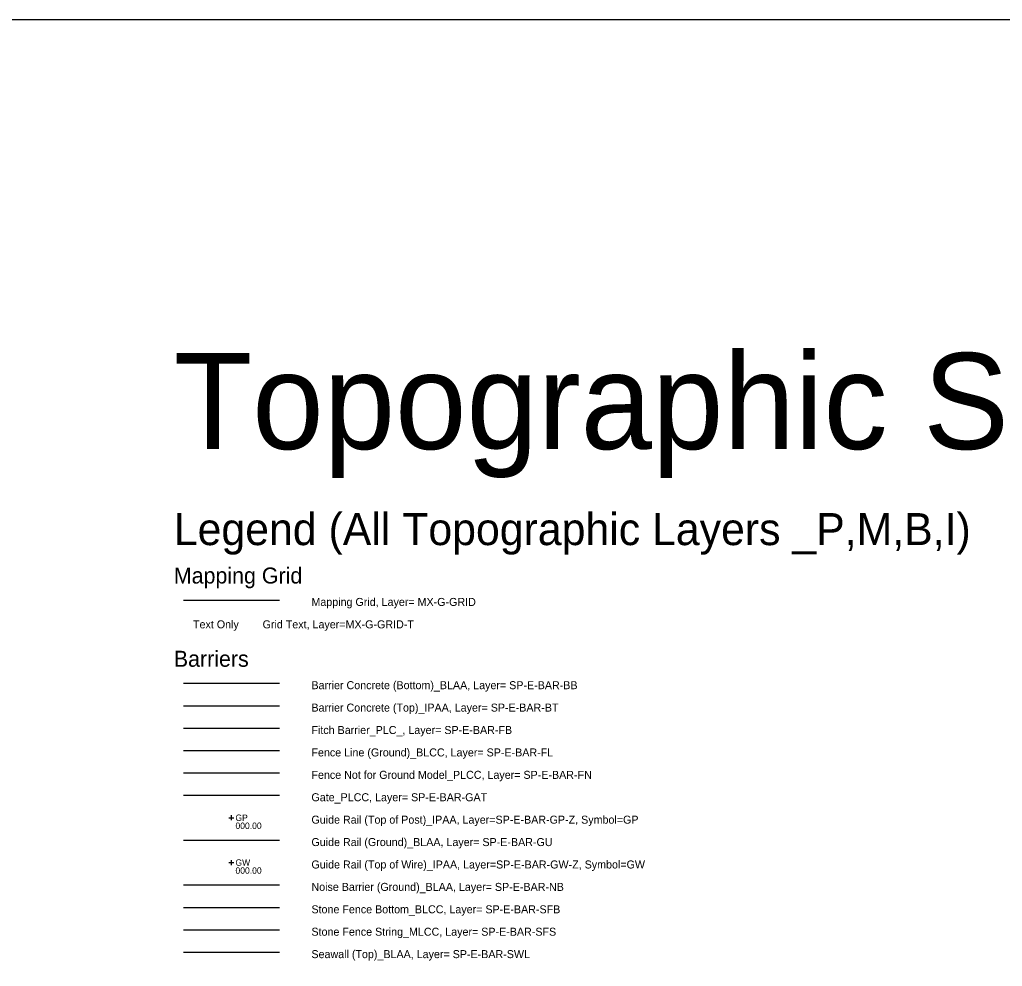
# Model space of a CAD drawing. Extents: x 500528 to 502626, y 4210261 to 4212624.
# Drawn here: x 500835.4 to 501142.4, y 4212328.2 to 4212623.9 of the extents above; entities that cross this region are included whole.
import ezdxf

# ---------------------------------------------------------------- set-up
doc = ezdxf.new("R2010")
doc.units = 0
for name, color, linetype in [('Default', 7, 'Continuous'), ('MX-G-GRID', 7, 'Continuous'), ('MX-G-GRID-T', 7, 'Continuous'), ('SP-E-BAR-BB', 7, 'Continuous'), ('SP-E-BAR-BT', 7, 'Continuous'), ('SP-E-BAR-FB', 7, 'Continuous'), ('SP-E-BAR-FL', 7, 'Continuous'), ('SP-E-BAR-FN', 7, 'Continuous'), ('SP-E-BAR-GAT', 7, 'Continuous'), ('SP-E-BAR-GP-Z', 7, 'Continuous'), ('SP-E-BAR-GU', 7, 'Continuous'), ('SP-E-BAR-GW-Z', 7, 'Continuous'), ('SP-E-BAR-NB', 7, 'Continuous'), ('SP-E-BAR-SFB', 7, 'Continuous'), ('SP-E-BAR-SFS', 7, 'Continuous'), ('SP-E-BAR-SWL', 7, 'Continuous'), ('SP-E-BAR-T', 7, 'Continuous')]:
    doc.layers.add(name, color=color, linetype=linetype)

# ---------------------------------------------------------------- blocks, each defined once
blk = doc.blocks.new('GP')
at = {"layer": 'SP-E-BAR-GP-Z'}
for points in [[(-0.08, 0), (0.08, 0)], [(0, -0.08), (0, 0.08)]]:
    blk.add_lwpolyline(points, dxfattribs=at)
at = {"layer": 'SP-E-BAR-T'}
for s, p in [('GP', (0.126, -0.1)), ('000.00', (0.126, -0.35))]:
    blk.add_text(s, height=0.2, dxfattribs=at).set_placement(p)
blk = doc.blocks.new('GW')
at = {"layer": 'SP-E-BAR-GW-Z'}
for points in [[(-0.08, 0), (0.08, 0)], [(0, -0.08), (0, 0.08)]]:
    blk.add_lwpolyline(points, dxfattribs=at)
at = {"layer": 'SP-E-BAR-T'}
for s, p in [('GW', (0.126, -0.1)), ('000.00', (0.126, -0.35))]:
    blk.add_text(s, height=0.2, dxfattribs=at).set_placement(p)

msp = doc.modelspace()

# ---------------------------------------------------------------- linework, layer by layer
at = {"layer": 'Default'}
msp.add_lwpolyline([(500528.35, 4212623.85), (500528.35, 4210260.5), (502626.48, 4210260.5), (502626.48, 4212623.85), (500528.35, 4212623.85)], dxfattribs=at)
msp.add_lwpolyline([(500528.35, 4210260.5), (502626.48, 4210260.5), (502626.48, 4212623.85), (500528.35, 4212623.85)], close=True, dxfattribs=at)
at = {"layer": 'MX-G-GRID'}
msp.add_line((500886.55, 4212442.59), (500916.55, 4212442.59), dxfattribs=at)
at = {"layer": 'SP-E-BAR-BB'}
msp.add_line((500886.55, 4212416.59), (500916.55, 4212416.59), dxfattribs=at)
at = {"layer": 'SP-E-BAR-BT'}
msp.add_line((500886.55, 4212409.59), (500916.55, 4212409.59), dxfattribs=at)
at = {"layer": 'SP-E-BAR-FB'}
msp.add_line((500886.55, 4212402.59), (500916.55, 4212402.59), dxfattribs=at)
at = {"layer": 'SP-E-BAR-FL'}
msp.add_line((500886.55, 4212395.59), (500916.55, 4212395.59), dxfattribs=at)
at = {"layer": 'SP-E-BAR-FN'}
msp.add_line((500886.55, 4212388.59), (500916.55, 4212388.59), dxfattribs=at)
at = {"layer": 'SP-E-BAR-GAT'}
msp.add_line((500886.55, 4212381.59), (500916.55, 4212381.59), dxfattribs=at)
at = {"layer": 'SP-E-BAR-GU'}
msp.add_line((500886.55, 4212367.59), (500916.55, 4212367.59), dxfattribs=at)
at = {"layer": 'SP-E-BAR-NB'}
msp.add_line((500886.55, 4212353.59), (500916.55, 4212353.59), dxfattribs=at)
at = {"layer": 'SP-E-BAR-SFB'}
msp.add_line((500886.55, 4212346.59), (500916.55, 4212346.59), dxfattribs=at)
at = {"layer": 'SP-E-BAR-SFS'}
msp.add_line((500886.55, 4212339.59), (500916.55, 4212339.59), dxfattribs=at)
at = {"layer": 'SP-E-BAR-SWL'}
msp.add_line((500886.55, 4212332.59), (500916.55, 4212332.59), dxfattribs=at)

# ---------------------------------------------------------------- block references
at = {"layer": 'SP-E-BAR-GP-Z', "xscale": 10, "yscale": 10}
msp.add_blockref('GP', (500901.55, 4212374.59), dxfattribs=at)
at = {"layer": 'SP-E-BAR-GW-Z', "xscale": 10, "yscale": 10}
msp.add_blockref('GW', (500901.55, 4212360.59), dxfattribs=at)

# ---------------------------------------------------------------- texts
at = {"layer": 'Default'}
for s, height, p in [('Topographic Survey Legend _Rev0 ', 30, (500883.55, 4212489.74)), ('Legend (All Topographic Layers _P,M,B,I) ', 10, (500883.55, 4212459.74)), ('Mapping Grid ', 5, (500883.55, 4212447.74)), ('Barriers ', 5, (500883.55, 4212421.74))]:
    msp.add_text(s, height=height, dxfattribs=at).set_placement(p)
at = {"layer": 'MX-G-GRID'}
msp.add_text('Mapping Grid, Layer= MX-G-GRID ', height=2.5, dxfattribs=at).set_placement((500926.55, 4212440.74))
at = {"layer": 'MX-G-GRID-T'}
msp.add_text('Text Only        Grid Text, Layer=MX-G-GRID-T', height=2.5, dxfattribs=at).set_placement((500889.55, 4212433.74))
at = {"layer": 'SP-E-BAR-BB'}
msp.add_text('Barrier Concrete (Bottom)_BLAA, Layer= SP-E-BAR-BB ', height=2.5, dxfattribs=at).set_placement((500926.55, 4212414.74))
at = {"layer": 'SP-E-BAR-BT'}
msp.add_text('Barrier Concrete (Top)_IPAA, Layer= SP-E-BAR-BT ', height=2.5, dxfattribs=at).set_placement((500926.55, 4212407.74))
at = {"layer": 'SP-E-BAR-FB'}
msp.add_text('Fitch Barrier_PLC_, Layer= SP-E-BAR-FB ', height=2.5, dxfattribs=at).set_placement((500926.55, 4212400.74))
at = {"layer": 'SP-E-BAR-FL'}
msp.add_text('Fence Line (Ground)_BLCC, Layer= SP-E-BAR-FL ', height=2.5, dxfattribs=at).set_placement((500926.55, 4212393.74))
at = {"layer": 'SP-E-BAR-FN'}
msp.add_text('Fence Not for Ground Model_PLCC, Layer= SP-E-BAR-FN ', height=2.5, dxfattribs=at).set_placement((500926.55, 4212386.74))
at = {"layer": 'SP-E-BAR-GAT'}
msp.add_text('Gate_PLCC, Layer= SP-E-BAR-GAT ', height=2.5, dxfattribs=at).set_placement((500926.55, 4212379.74))
at = {"layer": 'SP-E-BAR-GP-Z'}
msp.add_text('Guide Rail (Top of Post)_IPAA, Layer=SP-E-BAR-GP-Z, Symbol=GP ', height=2.5, dxfattribs=at).set_placement((500926.55, 4212372.74))
at = {"layer": 'SP-E-BAR-GU'}
msp.add_text('Guide Rail (Ground)_BLAA, Layer= SP-E-BAR-GU ', height=2.5, dxfattribs=at).set_placement((500926.55, 4212365.74))
at = {"layer": 'SP-E-BAR-GW-Z'}
msp.add_text('Guide Rail (Top of Wire)_IPAA, Layer=SP-E-BAR-GW-Z, Symbol=GW ', height=2.5, dxfattribs=at).set_placement((500926.55, 4212358.74))
at = {"layer": 'SP-E-BAR-NB'}
msp.add_text('Noise Barrier (Ground)_BLAA, Layer= SP-E-BAR-NB ', height=2.5, dxfattribs=at).set_placement((500926.55, 4212351.74))
at = {"layer": 'SP-E-BAR-SFB'}
msp.add_text('Stone Fence Bottom_BLCC, Layer= SP-E-BAR-SFB ', height=2.5, dxfattribs=at).set_placement((500926.55, 4212344.74))
at = {"layer": 'SP-E-BAR-SFS'}
msp.add_text('Stone Fence String_MLCC, Layer= SP-E-BAR-SFS ', height=2.5, dxfattribs=at).set_placement((500926.55, 4212337.74))
at = {"layer": 'SP-E-BAR-SWL'}
msp.add_text('Seawall (Top)_BLAA, Layer= SP-E-BAR-SWL ', height=2.5, dxfattribs=at).set_placement((500926.55, 4212330.74))

doc.saveas('drawing.dxf')
